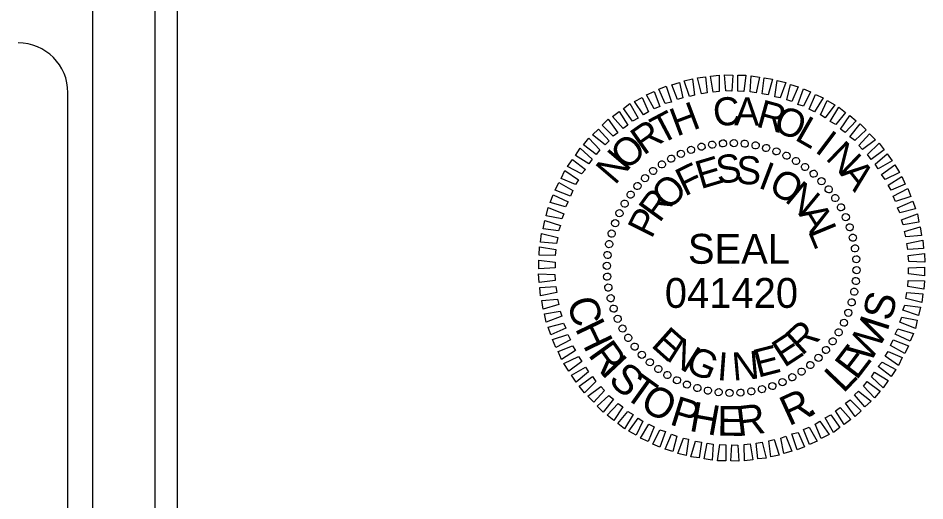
# Model space of a CAD drawing. Extents: x 2241278 to 2254132, y 649924 to 670434.
# Drawn here: x 2252819 to 2253730, y 661490 to 661974 of the extents above; entities that cross this region are included whole.
import ezdxf

# ---------------------------------------------------------------- set-up
doc = ezdxf.new("R2010")
doc.units = 0
for name, color, linetype in [('Sheet PE Seal Cell', 7, 'Continuous'), ('Sheet Plot Border Inside CELL', 7, 'Continuous'), ('Sheet Plot Border Outside CELL', 7, 'Continuous'), ('Sheet Title CELL', 7, 'Continuous')]:
    doc.layers.add(name, color=color, linetype=linetype)

msp = doc.modelspace()

# ---------------------------------------------------------------- linework, layer by layer
at = {"layer": 'Sheet PE Seal Cell'}
for p, q in [((2253494.52, 661842.2), (2253494.52, 661842.2)), ((2253505.02, 661845.2), (2253505.02, 661845.2)), ((2253516.02, 661847.2), (2253516.02, 661847.2)), ((2253526.77, 661848.7), (2253526.77, 661848.7)), ((2253537.77, 661848.95), (2253537.77, 661848.95)), ((2253548.77, 661848.2), (2253548.77, 661848.2)), ((2253559.52, 661846.45), (2253559.52, 661846.45)), ((2253570.02, 661844.2), (2253570.02, 661844.2)), ((2253580.52, 661840.7), (2253580.52, 661840.7)), ((2253474.77, 661833.2), (2253474.77, 661833.2)), ((2253484.52, 661838.2), (2253484.52, 661838.2)), ((2253590.52, 661836.2), (2253590.52, 661836.2)), ((2253465.27, 661827.45), (2253465.27, 661827.45)), ((2253600.27, 661831.2), (2253600.27, 661831.2)), ((2253609.27, 661824.95), (2253609.27, 661824.95)), ((2253448.27, 661813.7), (2253448.27, 661813.7)), ((2253456.52, 661821.2), (2253456.52, 661821.2)), ((2253618.02, 661818.2), (2253618.02, 661818.2)), ((2253440.77, 661805.95), (2253440.77, 661805.95)), ((2253625.77, 661810.7), (2253625.77, 661810.7)), ((2253434.02, 661797.2), (2253434.02, 661797.2)), ((2253633.27, 661802.45), (2253633.27, 661802.45)), ((2253427.77, 661788.2), (2253427.77, 661788.2)), ((2253639.52, 661793.7), (2253639.52, 661793.7)), ((2253422.77, 661778.45), (2253422.77, 661778.45)), ((2253645.27, 661784.2), (2253645.27, 661784.2)), ((2253418.27, 661768.45), (2253418.27, 661768.45)), ((2253650.27, 661774.45), (2253650.27, 661774.45)), ((2253654.27, 661764.45), (2253654.27, 661764.45)), ((2253414.77, 661757.95), (2253414.77, 661757.95)), ((2253657.27, 661753.95), (2253657.27, 661753.95)), ((2253412.52, 661747.45), (2253412.52, 661747.45)), ((2253659.27, 661742.95), (2253659.27, 661742.95)), ((2253410.77, 661736.7), (2253410.77, 661736.7)), ((2253660.77, 661732.2), (2253660.77, 661732.2)), ((2253410.02, 661725.7), (2253410.02, 661725.7)), ((2253535.52, 661723.45), (2253535.52, 661723.45)), ((2253410.27, 661714.7), (2253410.27, 661714.7)), ((2253661.02, 661721.2), (2253661.02, 661721.2)), ((2253411.77, 661703.95), (2253411.77, 661703.95)), ((2253660.27, 661710.2), (2253660.27, 661710.2)), ((2253658.52, 661699.45), (2253658.52, 661699.45)), ((2253413.77, 661692.95), (2253413.77, 661692.95)), ((2253656.27, 661688.95), (2253656.27, 661688.95)), ((2253416.77, 661682.45), (2253416.77, 661682.45)), ((2253652.77, 661678.45), (2253652.77, 661678.45)), ((2253420.77, 661672.45), (2253420.77, 661672.45)), ((2253648.27, 661668.45), (2253648.27, 661668.45)), ((2253425.77, 661662.7), (2253425.77, 661662.7)), ((2253643.27, 661658.7), (2253643.27, 661658.7)), ((2253431.52, 661653.2), (2253431.52, 661653.2)), ((2253637.02, 661649.7), (2253637.02, 661649.7)), ((2253437.77, 661644.45), (2253437.77, 661644.45)), ((2253630.27, 661640.95), (2253630.27, 661640.95)), ((2253445.27, 661636.2), (2253445.27, 661636.2)), ((2253622.77, 661633.2), (2253622.77, 661633.2)), ((2253453.02, 661628.7), (2253453.02, 661628.7)), ((2253461.77, 661621.95), (2253461.77, 661621.95)), ((2253614.52, 661625.7), (2253614.52, 661625.7)), ((2253470.77, 661615.7), (2253470.77, 661615.7)), ((2253596.27, 661613.7), (2253596.27, 661613.7)), ((2253605.77, 661619.45), (2253605.77, 661619.45)), ((2253480.52, 661610.7), (2253480.52, 661610.7)), ((2253490.52, 661606.2), (2253490.52, 661606.2)), ((2253576.52, 661604.7), (2253576.52, 661604.7)), ((2253586.52, 661608.7), (2253586.52, 661608.7)), ((2253501.02, 661602.7), (2253501.02, 661602.7)), ((2253511.52, 661600.45), (2253511.52, 661600.45)), ((2253522.27, 661598.7), (2253522.27, 661598.7)), ((2253533.27, 661597.95), (2253533.27, 661597.95)), ((2253544.27, 661598.2), (2253544.27, 661598.2)), ((2253555.02, 661599.7), (2253555.02, 661599.7)), ((2253566.02, 661601.7), (2253566.02, 661601.7))]:
    msp.add_line(p, q, dxfattribs=at)
for points in [[(2253505.02, 661898.45), (2253501.02, 661914.45), (2253509.27, 661915.2), (2253511.02, 661899.2)], [(2253517.02, 661899.95), (2253514.27, 661915.95), (2253522.77, 661916.95), (2253523.02, 661900.7)], [(2253529.52, 661901.2), (2253528.27, 661917.45), (2253536.52, 661917.2), (2253535.52, 661900.95)], [(2253541.52, 661900.95), (2253541.52, 661917.2), (2253549.77, 661916.95), (2253547.52, 661900.7)], [(2253554.02, 661900.2), (2253555.02, 661916.45), (2253563.27, 661914.95), (2253560.02, 661899.2)], [(2253566.02, 661898.2), (2253568.27, 661914.2), (2253576.52, 661912.95), (2253572.02, 661897.45)], [(2253468.77, 661888.45), (2253462.27, 661902.95), (2253469.77, 661905.95), (2253475.02, 661889.95)], [(2253481.02, 661892.45), (2253475.27, 661907.45), (2253483.02, 661909.7), (2253486.27, 661894.2)], [(2253493.02, 661895.7), (2253487.77, 661911.45), (2253496.27, 661913.2), (2253498.27, 661896.95)], [(2253578.77, 661895.45), (2253581.27, 661911.7), (2253589.77, 661909.7), (2253584.02, 661894.2)], [(2253590.77, 661892.2), (2253594.52, 661907.7), (2253602.27, 661905.2), (2253596.02, 661890.45)], [(2253457.77, 661883.2), (2253449.77, 661897.2), (2253457.52, 661900.7), (2253463.27, 661885.45)], [(2253602.02, 661887.7), (2253607.77, 661903.45), (2253614.77, 661900.45), (2253607.77, 661885.95)], [(2253613.27, 661882.95), (2253619.52, 661897.7), (2253627.27, 661894.2), (2253618.77, 661880.2)], [(2253436.02, 661870.95), (2253426.77, 661883.7), (2253433.27, 661888.45), (2253441.52, 661873.95)], [(2253447.02, 661877.2), (2253437.77, 661890.7), (2253445.52, 661894.7), (2253451.77, 661880.2)], [(2253624.77, 661877.2), (2253631.52, 661891.45), (2253639.02, 661887.2), (2253629.52, 661874.2)], [(2253426.52, 661863.45), (2253415.77, 661875.45), (2253422.52, 661880.7), (2253431.27, 661866.7)], [(2253634.52, 661870.45), (2253643.27, 661884.95), (2253649.77, 661879.7), (2253640.02, 661867.45)], [(2253416.52, 661855.7), (2253405.52, 661866.7), (2253411.52, 661872.7), (2253421.27, 661859.2)], [(2253644.77, 661862.95), (2253654.02, 661876.7), (2253660.52, 661871.2), (2253649.52, 661859.45)], [(2253654.27, 661855.2), (2253664.52, 661868.2), (2253670.52, 661862.2), (2253659.02, 661851.45)], [(2253408.27, 661846.95), (2253395.52, 661857.2), (2253401.77, 661862.95), (2253412.27, 661850.95)], [(2253399.52, 661837.45), (2253386.52, 661847.2), (2253392.02, 661853.7), (2253403.02, 661841.95)], [(2253663.27, 661846.45), (2253674.02, 661858.2), (2253680.02, 661852.2), (2253667.02, 661842.45)], [(2253392.02, 661827.95), (2253378.52, 661836.45), (2253383.27, 661843.7), (2253395.27, 661832.7)], [(2253672.02, 661837.45), (2253683.52, 661848.7), (2253688.77, 661841.95), (2253675.52, 661832.45)], [(2253384.52, 661817.95), (2253370.52, 661825.45), (2253375.52, 661832.45), (2253388.52, 661822.45)], [(2253679.52, 661827.7), (2253691.77, 661838.2), (2253696.52, 661830.95), (2253682.52, 661822.95)], [(2253686.02, 661817.45), (2253699.27, 661826.95), (2253704.02, 661819.45), (2253689.52, 661812.45)], [(2253378.52, 661807.2), (2253364.27, 661813.45), (2253368.02, 661821.2), (2253381.52, 661811.95)], [(2253692.52, 661806.45), (2253706.52, 661815.2), (2253709.77, 661807.45), (2253695.52, 661801.7)], [(2253373.52, 661795.7), (2253358.02, 661801.45), (2253361.77, 661809.2), (2253376.02, 661801.2)], [(2253368.52, 661784.7), (2253353.02, 661789.2), (2253356.27, 661796.95), (2253371.27, 661789.95)], [(2253697.52, 661795.7), (2253712.27, 661803.2), (2253715.52, 661795.2), (2253700.02, 661790.2)], [(2253702.02, 661783.95), (2253717.27, 661790.45), (2253720.02, 661782.7), (2253704.52, 661778.7)], [(2253364.77, 661772.7), (2253349.27, 661775.95), (2253351.02, 661784.2), (2253366.77, 661777.95)], [(2253706.02, 661771.95), (2253722.02, 661777.7), (2253723.52, 661769.45), (2253707.77, 661766.7)], [(2253361.52, 661760.7), (2253346.02, 661762.7), (2253347.77, 661771.2), (2253363.52, 661765.95)], [(2253709.02, 661759.95), (2253724.77, 661764.7), (2253726.27, 661756.2), (2253710.52, 661754.7)], [(2253359.52, 661747.95), (2253343.52, 661749.45), (2253344.52, 661757.95), (2253360.77, 661753.95)], [(2253711.27, 661747.95), (2253727.52, 661751.45), (2253728.27, 661742.95), (2253712.27, 661741.95)], [(2253358.27, 661735.95), (2253342.02, 661736.45), (2253342.52, 661744.7), (2253358.77, 661741.95)], [(2253358.02, 661723.45), (2253341.77, 661722.7), (2253341.77, 661731.2), (2253358.02, 661729.45)], [(2253712.77, 661735.95), (2253729.02, 661737.95), (2253729.52, 661729.45), (2253713.27, 661729.95)], [(2253713.02, 661723.45), (2253729.27, 661724.2), (2253729.27, 661715.7), (2253713.02, 661717.45)], [(2253358.27, 661710.95), (2253342.02, 661708.95), (2253341.52, 661717.45), (2253357.77, 661716.95)], [(2253359.77, 661698.95), (2253343.52, 661695.45), (2253342.77, 661703.95), (2253358.77, 661704.95)], [(2253712.77, 661710.95), (2253729.02, 661710.45), (2253728.52, 661702.2), (2253712.27, 661704.95)], [(2253711.52, 661698.95), (2253727.52, 661697.45), (2253726.52, 661688.95), (2253710.27, 661692.95)], [(2253362.02, 661686.95), (2253346.27, 661682.2), (2253344.77, 661690.7), (2253360.52, 661692.2)], [(2253709.52, 661686.2), (2253725.02, 661684.2), (2253723.27, 661675.7), (2253707.52, 661680.95)], [(2253365.02, 661674.95), (2253349.02, 661669.2), (2253347.52, 661677.45), (2253363.27, 661680.2)], [(2253369.02, 661662.95), (2253353.77, 661656.45), (2253351.02, 661664.2), (2253366.52, 661668.2)], [(2253706.27, 661674.2), (2253721.77, 661670.95), (2253720.02, 661662.7), (2253704.27, 661668.95)], [(2253702.52, 661662.2), (2253718.02, 661657.7), (2253714.77, 661649.95), (2253699.77, 661656.95)], [(2253373.52, 661651.2), (2253358.77, 661643.7), (2253355.52, 661651.7), (2253371.02, 661656.7)], [(2253697.52, 661651.2), (2253713.02, 661645.45), (2253709.27, 661637.7), (2253695.02, 661645.7)], [(2253378.52, 661640.45), (2253364.52, 661631.7), (2253361.27, 661639.45), (2253375.52, 661645.2)], [(2253385.02, 661629.45), (2253371.77, 661619.95), (2253367.02, 661627.45), (2253381.52, 661634.45)], [(2253692.52, 661639.7), (2253706.77, 661633.45), (2253703.02, 661625.7), (2253689.52, 661634.95)], [(2253391.52, 661619.2), (2253379.27, 661608.7), (2253374.52, 661615.95), (2253388.52, 661623.95)], [(2253686.52, 661628.95), (2253700.52, 661621.45), (2253695.52, 661614.45), (2253682.52, 661624.45)], [(2253399.02, 661609.45), (2253387.52, 661598.2), (2253382.27, 661604.95), (2253395.52, 661614.45)], [(2253679.02, 661618.95), (2253692.52, 661610.45), (2253687.77, 661603.2), (2253675.77, 661614.2)], [(2253407.77, 661600.45), (2253397.02, 661588.7), (2253391.02, 661594.7), (2253404.02, 661604.45)], [(2253671.52, 661609.45), (2253684.52, 661599.7), (2253679.02, 661593.2), (2253668.02, 661604.95)], [(2253416.77, 661591.7), (2253406.52, 661578.7), (2253400.52, 661584.7), (2253412.02, 661595.45)], [(2253662.77, 661599.95), (2253675.52, 661589.7), (2253669.27, 661583.95), (2253658.77, 661595.95)], [(2253426.27, 661583.95), (2253417.02, 661570.2), (2253410.52, 661575.7), (2253421.52, 661587.45)], [(2253654.52, 661591.2), (2253665.52, 661580.2), (2253659.52, 661574.2), (2253649.77, 661587.7)], [(2253436.52, 661576.45), (2253427.77, 661561.95), (2253421.27, 661567.2), (2253431.02, 661579.45)], [(2253644.52, 661583.45), (2253655.27, 661571.45), (2253648.52, 661566.2), (2253639.77, 661580.2)], [(2253446.27, 661569.7), (2253439.52, 661555.45), (2253432.02, 661559.7), (2253441.52, 661572.7)], [(2253624.02, 661569.7), (2253633.27, 661556.2), (2253625.52, 661552.2), (2253619.27, 661566.7)], [(2253635.02, 661575.95), (2253644.27, 661563.2), (2253637.77, 661558.45), (2253629.52, 661572.95)], [(2253457.77, 661563.95), (2253451.52, 661549.2), (2253443.77, 661552.7), (2253452.27, 661566.7)], [(2253469.02, 661559.2), (2253463.27, 661543.45), (2253456.27, 661546.45), (2253463.27, 661560.95)], [(2253602.27, 661558.45), (2253608.77, 661543.95), (2253601.27, 661540.95), (2253596.02, 661556.95)], [(2253613.27, 661563.7), (2253621.27, 661549.7), (2253613.52, 661546.2), (2253607.77, 661561.45)], [(2253480.27, 661554.7), (2253476.52, 661539.2), (2253468.77, 661541.7), (2253475.02, 661556.45)], [(2253492.27, 661551.45), (2253489.77, 661535.2), (2253481.27, 661537.2), (2253487.02, 661552.7)], [(2253505.02, 661548.7), (2253502.77, 661532.7), (2253494.52, 661533.95), (2253499.02, 661549.45)], [(2253578.02, 661551.2), (2253583.27, 661535.45), (2253574.77, 661533.7), (2253572.77, 661549.95)], [(2253590.02, 661554.45), (2253595.77, 661539.45), (2253588.02, 661537.2), (2253584.77, 661552.7)], [(2253517.02, 661546.7), (2253516.02, 661530.45), (2253507.77, 661531.95), (2253511.02, 661547.7)], [(2253529.52, 661545.95), (2253529.52, 661529.7), (2253521.27, 661529.95), (2253523.52, 661546.2)], [(2253541.52, 661545.7), (2253542.77, 661529.45), (2253534.52, 661529.7), (2253535.52, 661545.95)], [(2253554.02, 661546.95), (2253556.77, 661530.95), (2253548.27, 661529.95), (2253548.02, 661546.2)], [(2253566.02, 661548.45), (2253570.02, 661532.45), (2253561.77, 661531.7), (2253560.02, 661547.7)]]:
    msp.add_lwpolyline(points, close=True, dxfattribs=at)
for centre, major_axis in [((2253515.9, 661847.31), (-0.56, 3.56)), ((2253526.77, 661848.55), (-0.25, 3.59)), ((2253537.71, 661848.83), (0.06, 3.6)), ((2253548.62, 661848.17), (0.38, 3.58)), ((2253559.44, 661846.55), (0.69, 3.53)), ((2253484.51, 661838.01), (-1.46, 3.29)), ((2253494.69, 661842.02), (-1.17, 3.4)), ((2253505.18, 661845.13), (-0.87, 3.49)), ((2253570.08, 661843.99), (0.99, 3.46)), ((2253580.46, 661840.52), (1.29, 3.36)), ((2253465.39, 661827.41), (-2.01, 2.98)), ((2253474.72, 661833.13), (-1.75, 3.15)), ((2253590.49, 661836.16), (1.58, 3.24)), ((2253600.1, 661830.94), (1.85, 3.09)), ((2253456.6, 661820.91), (-2.27, 2.8)), ((2253609.22, 661824.9), (2.12, 2.91)), ((2253448.41, 661813.66), (-2.5, 2.59)), ((2253617.79, 661818.09), (2.36, 2.72)), ((2253625.72, 661810.56), (2.59, 2.5)), ((2253440.88, 661805.72), (-2.72, 2.36)), ((2253632.97, 661802.37), (2.8, 2.27)), ((2253434.07, 661797.16), (-2.91, 2.12)), ((2253639.48, 661793.58), (2.98, 2.01)), ((2253428.03, 661788.04), (-3.09, 1.85)), ((2253645.19, 661784.25), (3.15, 1.75)), ((2253422.81, 661778.42), (-3.24, 1.58)), ((2253650.08, 661774.46), (3.29, 1.46)), ((2253418.45, 661768.39), (-3.36, 1.29)), ((2253654.08, 661764.28), (3.4, 1.17)), ((2253414.97, 661758.02), (-3.46, 0.99)), ((2253412.42, 661747.38), (-3.53, 0.69)), ((2253657.19, 661753.79), (3.49, 0.87)), ((2253410.8, 661736.56), (-3.58, 0.38)), ((2253659.37, 661743.07), (3.56, 0.56)), ((2253660.61, 661732.2), (3.59, 0.25)), ((2253410.14, 661725.64), (-3.6, 0.06)), ((2253660.9, 661721.26), (3.6, -0.06)), ((2253410.42, 661714.71), (-3.59, -0.25)), ((2253660.23, 661710.34), (3.58, -0.38)), ((2253411.66, 661703.84), (-3.56, -0.56)), ((2253413.84, 661693.12), (-3.49, -0.87)), ((2253658.61, 661699.53), (3.53, -0.69)), ((2253416.95, 661682.63), (-3.4, -1.17)), ((2253656.06, 661688.89), (3.46, -0.99)), ((2253420.96, 661672.45), (-3.29, -1.46)), ((2253652.59, 661678.51), (3.36, -1.29)), ((2253648.23, 661668.48), (3.24, -1.58)), ((2253425.84, 661662.66), (-3.15, -1.75)), ((2253643.01, 661658.87), (3.09, -1.85)), ((2253431.56, 661653.33), (-2.98, -2.01)), ((2253636.97, 661649.74), (2.91, -2.12)), ((2253438.06, 661644.54), (-2.8, -2.27)), ((2253445.31, 661636.34), (-2.59, -2.5)), ((2253630.16, 661641.18), (2.72, -2.36)), ((2253453.25, 661628.81), (-2.36, -2.72)), ((2253622.63, 661633.25), (2.5, -2.59)), ((2253461.81, 661622), (-2.12, -2.91)), ((2253605.64, 661619.49), (2.01, -2.98)), ((2253614.43, 661626), (2.27, -2.8)), ((2253470.93, 661615.96), (-1.85, -3.09)), ((2253480.54, 661610.74), (-1.58, -3.24)), ((2253586.52, 661608.89), (1.46, -3.29)), ((2253596.31, 661613.78), (1.75, -3.15)), ((2253490.58, 661606.38), (-1.29, -3.36)), ((2253500.95, 661602.91), (-0.99, -3.46)), ((2253511.59, 661600.36), (-0.69, -3.53)), ((2253565.85, 661601.78), (0.87, -3.49)), ((2253576.34, 661604.88), (1.17, -3.4)), ((2253522.41, 661598.74), (-0.38, -3.58)), ((2253533.33, 661598.07), (-0.06, -3.6)), ((2253544.26, 661598.36), (0.25, -3.59)), ((2253555.13, 661599.6), (0.56, -3.56))]:
    msp.add_ellipse(centre, major_axis=major_axis, ratio=0.999708, dxfattribs=at)
at = {"layer": 'Sheet Plot Border Inside CELL'}
msp.add_lwpolyline([(2244623.77, 661011.36), (2252956.27, 661011.36), (2252956.27, 666286.86), (2244623.77, 666286.86)], close=True, dxfattribs=at)
at = {"layer": 'Sheet Plot Border Outside CELL'}
msp.add_lwpolyline([(2252978.77, 666399.11), (2244558.77, 666399.11), (2244558.77, 660899.17), (2252978.77, 660899.17)], close=True, dxfattribs=at)
at = {"layer": 'Sheet Title CELL'}
for points in [[(2252893.77, 661074.17), (2252893.77, 666224.11)], [(2252868.77, 661099.17), (2252868.77, 661899.17)]]:
    msp.add_lwpolyline(points, dxfattribs=at)
msp.add_arc((2252818.79, 661899.4), 50, 0, 90, dxfattribs=at)

# ---------------------------------------------------------------- texts
at = {"layer": 'Sheet PE Seal Cell'}
for s, height, rotation, p in [('C', 28.19, 6.21987, (2253518.27, 661865.2)), ('H', 28.19, 20.61948, (2253480.27, 661855.2)), ('A', 28.19, 359.02032, (2253538.02, 661866.7)), ('R', 28.19, 344.6211, (2253559.02, 661865.7)), ('T', 28.19, 27.81977, (2253464.02, 661846.95)), ('O', 28.19, 337.42116, (2253575.77, 661861.95)), ('R', 28.19, 35.02051, (2253447.02, 661835.95)), ('L', 28.19, 330.22088, (2253597.77, 661852.7)), ('I', 28.19, 323.02014, (2253618.02, 661840.7)), ('O', 28.19, 42.22174, (2253429.77, 661820.45)), ('N', 28.19, 315.81891, (2253628.77, 661832.95)), ('N', 28.19, 49.4235, (2253418.27, 661805.95)), ('E', 28.19, 16.61107, (2253504.27, 661802.45)), ('S', 28.19, 7.25561, (2253521.52, 661807.7)), ('S', 28.19, 357.9004, (2253539.52, 661807.95)), ('F', 28.19, 25.96703, (2253488.27, 661794.95)), ('I', 28.19, 339.1896, (2253561.02, 661804.45)), ('A', 28.19, 308.61715, (2253643.52, 661818.2)), ('O', 28.19, 44.68124, (2253471.77, 661780.2)), ('O', 28.19, 329.83348, (2253571.02, 661800.95)), ('N', 28.19, 320.47661, (2253587.77, 661790.95)), ('R', 28.2, 54.03965, (2253463.02, 661767.95)), ('P', 28.2, 63.39889, (2253455.02, 661751.95)), ('A', 28.2, 301.76027, (2253602.02, 661777.95)), ('L', 28.2, 292.40085, (2253611.77, 661760.7)), ('SEAL', 29.991, 360, (2253491.52, 661727.7)), ('S', 29.99, 76.05447, (2253695.66, 661669.17)), ('C', 29.99, 286.20197, (2253369.77, 661689.97)), ('H', 29.99, 295.78413, (2253377.66, 661662.84)), ('R', 28.19, 42.48141, (2253606.02, 661634.7)), ('W', 29.99, 59.71844, (2253673.92, 661626.32)), ('I', 29.99, 72.25252, (2253691.71, 661658.67)), ('E', 28.19, 318.27689, (2253453.52, 661645.2)), ('E', 28.19, 33.12409, (2253588.27, 661622.95)), ('R', 29.99, 305.76811, (2253390.56, 661636.39)), ('N', 28.19, 327.63396, (2253468.52, 661631.7)), ('G', 28.19, 336.99024, (2253487.52, 661620.45)), ('N', 28.19, 5.05639, (2253537.02, 661610.2)), ('E', 28.19, 14.41176, (2253561.77, 661613.2)), ('E', 29.99, 52.60911, (2253660.84, 661609.93)), ('I', 29.99, 313.24837, (2253403.13, 661618.26)), ('I', 28.19, 355.7012, (2253520.27, 661610.95)), ('S', 29.99, 317.05032, (2253410.39, 661609.72)), ('L', 29.99, 46.33434, (2253647.68, 661596.92)), ('T', 29.99, 324.37603, (2253425.92, 661594.69)), ('O', 29.99, 331.17627, (2253441.93, 661582.62)), ('R', 29.99, 24.61995, (2253592.9, 661564.4)), ('P', 29.99, 342.73667, (2253472.06, 661566.72)), ('H', 29.99, 349.84601, (2253491.94, 661560.07)), ('R', 29.99, 6.93933, (2253541.89, 661554.48)), ('E', 29.99, 359.82999, (2253520.93, 661554.99)), ('.', 29.99, 32.10021, (2253613.12, 661573.22))]:
    msp.add_text(s, height=height, rotation=rotation, dxfattribs=at).set_placement(p)
msp.add_text('041420', height=29.991, dxfattribs=at).set_placement((2253468.32, 661683.41))

doc.saveas('drawing.dxf')
